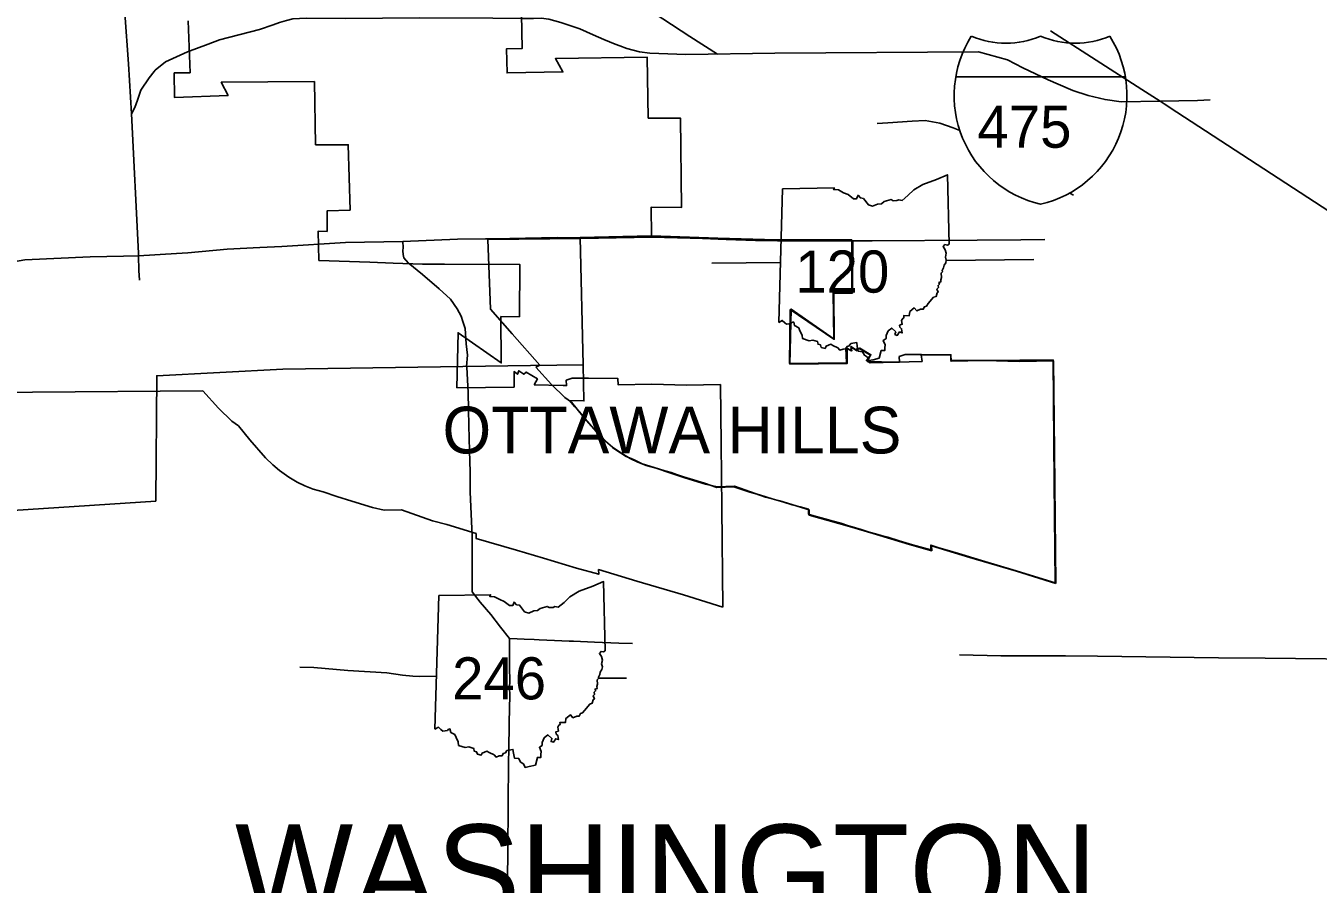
# Model space of a CAD drawing. Extents: x -232 to 448, y 619 to 1059.
# Drawn here: x 128.82 to 157.16, y 925.75 to 944.57 of the extents above; entities that cross this region are included whole.
import ezdxf

# ---------------------------------------------------------------- set-up
doc = ezdxf.new("R2010")
doc.units = 0
doc.layers.add('Default', color=7, linetype='Continuous')

msp = doc.modelspace()

# ---------------------------------------------------------------- linework, layer by layer
at = {"layer": 'Default'}
for p, q in [((149.212, 943.453), (152.932, 943.453)), ((145.332, 938.071), (145.414, 941)), ((145.332, 938.071), (145.414, 941)), ((137.791, 929.15), (137.873, 932.079)), ((137.791, 929.15), (137.873, 932.079))]:
    msp.add_line(p, q, dxfattribs=at)
for points in [[(142.542, 939.966), (142.53, 940.597), (143.197, 940.588), (143.174, 942.551), (142.47, 942.55), (142.445, 943.886), (140.432, 943.857), (140.597, 943.564), (139.374, 943.542), (139.361, 944.072), (139.707, 944.078), (139.685, 945.215), (143.284, 945.238), (143.246, 947.957), (145.167, 947.976), (145.165, 948.173), (140.633, 950.343), (140.619, 950.627), (145.149, 950.658), (145.086, 956.091), (145.054, 958.769)], [(143.987, 943.951), (143.381, 944.34), (142.789, 944.725), (142.086, 945.181), (141.31, 945.696), (141.182, 945.78)], [(131.138, 942.647), (131.072, 943.744), (130.99, 944.853)], [(132.38, 944.682), (132.423, 943.545), (132.075, 943.541), (132.078, 943.003), (133.254, 943.048), (133.105, 943.337), (135.151, 943.353)], [(132.818, 944.175), (133.069, 944.27), (133.944, 944.492), (134.245, 944.598), (134.383, 944.65), (134.537, 944.689), (134.675, 944.726), (134.97, 944.744), (135.833, 944.734), (137.454, 944.748), (139.058, 944.744), (139.679, 944.739)], [(139.679, 944.739), (139.952, 944.736), (140.119, 944.744), (140.287, 944.721), (140.553, 944.65), (140.965, 944.508), (141.264, 944.375), (141.496, 944.276), (141.745, 944.17), (141.848, 944.133)], [(153.293, 943.18), (151.289, 944.468)], [(131.637, 943.573), (131.658, 943.6), (131.88, 943.788), (132.362, 944.003), (132.818, 944.175)], [(141.848, 944.133), (141.998, 944.079), (142.28, 944.003), (142.503, 943.978), (143.291, 943.944), (145.246, 943.972), (149.707, 944.004), (150.348, 943.832), (150.684, 943.655), (151.237, 943.391)], [(131.138, 942.647), (131.213, 942.784), (131.271, 942.942), (131.345, 943.163), (131.525, 943.431), (131.637, 943.573)], [(151.237, 943.391), (151.456, 943.294), (151.779, 943.156), (152.118, 943.045), (152.487, 942.958), (152.839, 942.91), (153.694, 942.922)], [(135.151, 943.353), (135.174, 941.968)], [(153.785, 942.863), (153.694, 942.922), (153.293, 943.18)], [(153.694, 942.922), (154.515, 942.935), (154.788, 942.949)], [(154.06, 942.684), (153.785, 942.863)], [(131.287, 939.587), (131.138, 942.647)], [(158.045, 940.085), (154.06, 942.684)], [(147.487, 942.432), (147.721, 942.445), (148.256, 942.481), (148.544, 942.496), (148.861, 942.441), (149.156, 942.336), (149.301, 942.276)], [(135.174, 941.968), (135.89, 941.967), (135.935, 940.534)], [(145.414, 941), (146.55, 941.019), (146.532, 940.984), (146.64, 940.976), (146.753, 940.914), (146.85, 940.874), (146.968, 940.781), (147.038, 940.782), (147.068, 940.858), (147.122, 940.8), (147.186, 940.789), (147.297, 940.649), (147.388, 940.618), (147.498, 940.667), (147.58, 940.674), (147.639, 940.722), (147.795, 940.763), (147.839, 940.738), (147.921, 940.743), (147.963, 940.761), (148.035, 940.745), (148.162, 940.852), (148.292, 940.977), (148.493, 941.096), (148.793, 941.208), (149.03, 941.308), (149.064, 939.788)], [(145.414, 941), (146.55, 941.019), (146.532, 940.984), (146.64, 940.976), (146.753, 940.914), (146.85, 940.874), (146.968, 940.781), (147.038, 940.782), (147.068, 940.858), (147.122, 940.8), (147.186, 940.789), (147.297, 940.649), (147.388, 940.618), (147.498, 940.667), (147.58, 940.674), (147.639, 940.722), (147.795, 940.763), (147.839, 940.738), (147.921, 940.743), (147.963, 940.761), (148.035, 940.745), (148.162, 940.852), (148.292, 940.977), (148.493, 941.096), (148.793, 941.208), (149.03, 941.308), (149.064, 939.788)], [(151.713, 940.908), (151.792, 940.861)], [(135.935, 940.534), (135.43, 940.52), (135.425, 940.065)], [(135.425, 940.065), (135.231, 940.075), (135.247, 939.425)], [(132.124, 939.584), (132.369, 939.599), (133.232, 939.677), (133.951, 939.713)], [(133.951, 939.713), (134.436, 939.737), (135.826, 939.822), (137.086, 939.842)], [(137.086, 939.842), (138.284, 939.895), (138.9, 939.903)], [(137.086, 939.842), (137.095, 939.717), (137.088, 939.639), (137.095, 939.557), (137.108, 939.485), (137.207, 939.379), (137.517, 939.122), (137.886, 938.805), (138.133, 938.578), (138.28, 938.365), (138.368, 938.208), (138.406, 938.092), (138.451, 937.937), (138.477, 937.604), (138.503, 937.353), (138.486, 937.107), (138.487, 937.091)], [(138.9, 939.903), (139.083, 939.906), (140.472, 939.935), (141.528, 939.926), (142.29, 939.963), (142.472, 939.956)], [(140.991, 939.912), (138.952, 939.886)], [(138.952, 939.886), (139.008, 938.358)], [(141.042, 937.141), (140.979, 939.932), (142.542, 939.966)], [(142.549, 939.942), (140.991, 939.912)], [(142.472, 939.956), (143.127, 939.93), (143.314, 939.928), (144.179, 939.888), (144.831, 939.878), (145.298, 939.882), (146.451, 939.864), (146.793, 939.863)], [(142.542, 939.966), (143.994, 939.919), (145.275, 939.885), (146.93, 939.88)], [(146.537, 938.714), (146.946, 938.712), (146.954, 939.86), (145.3, 939.862), (144.82, 939.864), (144.18, 939.889), (143.663, 939.911), (142.549, 939.942)], [(150.618, 937.245), (149.106, 937.233), (149.106, 937.363), (148.456, 937.363), (148.472, 937.216), (147.336, 937.184), (147.254, 937.233), (147.352, 937.363), (147.108, 937.509), (147.011, 937.476), (146.913, 937.541), (146.93, 937.444), (146.8, 937.509), (146.816, 937.184), (145.566, 937.168), (145.582, 938.353), (146.54, 937.703), (146.524, 938.727), (146.93, 938.727), (146.93, 939.88)], [(146.793, 939.863), (147.382, 939.86), (149.683, 939.875)], [(149.064, 939.788), (149.029, 939.767), (148.975, 939.777), (148.938, 939.734), (148.983, 939.663), (149.005, 939.588), (148.986, 939.505), (149.004, 939.437), (148.992, 939.38), (148.957, 939.323), (148.946, 939.269), (148.917, 939.211), (148.919, 939.179), (148.891, 939.154), (148.896, 939.059), (148.882, 939.006), (148.887, 938.961), (148.842, 938.949), (148.852, 938.911), (148.824, 938.882), (148.83, 938.833), (148.797, 938.801), (148.829, 938.737), (148.804, 938.717), (148.783, 938.639), (148.725, 938.623), (148.609, 938.482), (148.569, 938.428), (148.523, 938.415), (148.498, 938.36), (148.441, 938.359), (148.356, 938.321), (148.301, 938.387), (148.204, 938.308), (148.193, 938.216), (148.07, 938.219), (148.075, 938.173), (148.048, 938.16), (148.023, 938.114), (148.038, 938.031), (147.98, 938.01), (147.987, 937.963), (148.024, 937.933), (148.04, 937.842), (147.979, 937.861), (147.93, 937.784), (147.878, 937.802), (147.895, 937.867), (147.809, 937.945), (147.727, 937.883), (147.684, 937.782), (147.683, 937.715), (147.622, 937.674), (147.661, 937.579), (147.654, 937.513), (147.656, 937.451), (147.579, 937.453), (147.533, 937.285)], [(149.064, 939.788), (149.029, 939.767), (148.975, 939.777), (148.938, 939.734), (148.983, 939.663), (149.005, 939.588), (148.986, 939.505), (149.004, 939.437), (148.992, 939.38), (148.957, 939.323), (148.946, 939.269), (148.917, 939.211), (148.919, 939.179), (148.891, 939.154), (148.896, 939.059), (148.882, 939.006), (148.887, 938.961), (148.842, 938.949), (148.852, 938.911), (148.824, 938.882), (148.83, 938.833), (148.797, 938.801), (148.829, 938.737), (148.804, 938.717), (148.783, 938.639), (148.725, 938.623), (148.609, 938.482), (148.569, 938.428), (148.523, 938.415), (148.498, 938.36), (148.441, 938.359), (148.356, 938.321), (148.301, 938.387), (148.204, 938.308), (148.193, 938.216), (148.07, 938.219), (148.075, 938.173), (148.048, 938.16), (148.023, 938.114), (148.038, 938.031), (147.98, 938.01), (147.987, 937.963), (148.024, 937.933), (148.04, 937.842), (147.979, 937.861), (147.93, 937.784), (147.878, 937.802), (147.895, 937.867), (147.809, 937.945), (147.727, 937.883), (147.684, 937.782), (147.683, 937.715), (147.622, 937.674), (147.661, 937.579), (147.654, 937.513), (147.656, 937.451), (147.579, 937.453), (147.533, 937.285)], [(149.683, 939.875), (150.637, 939.882), (151.162, 939.887)], [(117.861, 938.93), (119.236, 938.938), (119.978, 938.942), (120.576, 938.943), (121.517, 938.965), (123.244, 938.981), (123.805, 938.96), (124.811, 938.901), (125.624, 938.858), (125.876, 938.862), (126.169, 938.873), (126.746, 938.987), (127.511, 939.17), (128.505, 939.389), (128.801, 939.441), (130.232, 939.508), (130.961, 939.526)], [(130.961, 939.526), (131.29, 939.533)], [(131.29, 939.533), (131.287, 939.587)], [(131.29, 939.533), (132.124, 939.584)], [(131.315, 938.998), (131.3, 939.206), (131.29, 939.533)], [(135.247, 939.425), (136.362, 939.394), (136.878, 939.372), (137.518, 939.347), (137.998, 939.345), (139.652, 939.343), (139.645, 938.195), (139.236, 938.197)], [(149.002, 939.428), (150.926, 939.449)], [(143.861, 939.371), (145.369, 939.387)], [(147.272, 937.217), (147.34, 937.349), (147.094, 937.497), (147.044, 937.449), (146.929, 937.527), (146.901, 937.452), (146.829, 937.509), (146.828, 937.168), (145.575, 937.155), (145.6, 938.362), (146.547, 937.701), (146.537, 938.714)], [(139.008, 938.358), (139.485, 937.821), (140.094, 937.13)], [(139.236, 938.197), (139.245, 937.184), (138.298, 937.845), (138.274, 936.638), (139.527, 936.651), (139.527, 936.992), (139.599, 936.935), (139.628, 937.011), (139.743, 936.932), (139.793, 936.98), (140.039, 936.832), (139.97, 936.7)], [(147.533, 937.285), (147.4, 937.253), (147.308, 937.234), (147.276, 937.31), (147.21, 937.35), (147.167, 937.427), (147.073, 937.438), (147.05, 937.543), (147.04, 937.629), (146.911, 937.608), (146.875, 937.556), (146.829, 937.541), (146.803, 937.489), (146.74, 937.484), (146.673, 937.459), (146.629, 937.511), (146.519, 937.563), (146.47, 937.59), (146.367, 937.548), (146.345, 937.499), (146.262, 937.521), (146.243, 937.576), (146.193, 937.592), (146.182, 937.651), (146.076, 937.682), (145.995, 937.669), (145.851, 937.716), (145.843, 937.793), (145.794, 937.886), (145.768, 937.951), (145.677, 938.001), (145.659, 938.078), (145.63, 938.076), (145.604, 938.045), (145.503, 938.03), (145.463, 938.062), (145.406, 938.116), (145.332, 938.071)], [(147.533, 937.285), (147.4, 937.253), (147.308, 937.234), (147.276, 937.31), (147.21, 937.35), (147.167, 937.427), (147.073, 937.438), (147.05, 937.543), (147.04, 937.629), (146.911, 937.608), (146.875, 937.556), (146.829, 937.541), (146.803, 937.489), (146.74, 937.484), (146.673, 937.459), (146.629, 937.511), (146.519, 937.563), (146.47, 937.59), (146.367, 937.548), (146.345, 937.499), (146.262, 937.521), (146.243, 937.576), (146.193, 937.592), (146.182, 937.651), (146.076, 937.682), (145.995, 937.669), (145.851, 937.716), (145.843, 937.793), (145.794, 937.886), (145.768, 937.951), (145.677, 938.001), (145.659, 938.078), (145.63, 938.076), (145.604, 938.045), (145.503, 938.03), (145.463, 938.062), (145.406, 938.116), (145.332, 938.071)], [(149.847, 937.236), (149.108, 937.219), (149.105, 937.357), (148.462, 937.364), (148.1, 937.366), (147.972, 937.32), (147.977, 937.201), (147.902, 937.202), (147.272, 937.217)], [(150.612, 937.214), (149.847, 937.236)], [(150.618, 937.245), (151.349, 937.245), (151.372, 934.574), (151.395, 932.36), (150.539, 932.62)], [(151.358, 937.226), (150.612, 937.214)], [(151.405, 932.342), (151.381, 934.517), (151.369, 935.926), (151.358, 937.226)], [(131.674, 934.149), (131.689, 936.9), (134.454, 937.043), (139.887, 937.125), (141.042, 937.141)], [(138.487, 937.091), (138.517, 936.537), (138.529, 936.159), (138.535, 935.812), (138.55, 935.257), (138.56, 934.793), (138.567, 934.377)], [(140.094, 937.13), (140.002, 937.087)], [(140.002, 937.087), (140.346, 936.708), (140.641, 936.423), (140.786, 936.321)], [(150.539, 932.62), (150.12, 932.747), (149.777, 932.848), (149.344, 932.98), (149.075, 933.064), (148.82, 933.136), (148.663, 933.187), (148.668, 933.082), (148.264, 933.191), (147.968, 933.284), (147.725, 933.358), (147.576, 933.4), (147.449, 933.434), (147.314, 933.474), (147.135, 933.528), (147.012, 933.568), (146.841, 933.617), (146.688, 933.665), (146.52, 933.709), (146.341, 933.762), (146.182, 933.806), (146.026, 933.853), (145.979, 933.867), (145.986, 933.972), (145.803, 934.027), (145.621, 934.073), (145.441, 934.132), (145.184, 934.204), (144.909, 934.288), (144.696, 934.351), (144.519, 934.406), (144.345, 934.465), (143.975, 934.451), (143.703, 934.547), (143.458, 934.619), (143.242, 934.682), (143.085, 934.737), (142.969, 934.777), (142.834, 934.813), (142.599, 934.886), (142.332, 934.972), (142.244, 935.016), (142.171, 935.05), (142.097, 935.087), (141.983, 935.127), (141.857, 935.21), (141.777, 935.264), (141.686, 935.328), (141.534, 935.471), (141.444, 935.566), (141.341, 935.668), (141.217, 935.792), (141.107, 935.922), (140.959, 936.11), (140.858, 936.22), (140.744, 936.356), (141.059, 936.35), (141.042, 937.141)], [(139.97, 936.7), (140.6, 936.686), (140.676, 936.684), (140.671, 936.803), (140.799, 936.849), (141.161, 936.847), (141.803, 936.84), (141.806, 936.702), (142.545, 936.72)], [(142.545, 936.72), (143.31, 936.697)], [(143.31, 936.697), (144.056, 936.709)], [(144.056, 936.709), (144.067, 935.409), (144.079, 934.001), (144.103, 931.825)], [(132.7, 936.57), (128.966, 936.544), (127.156, 936.506), (126.227, 936.473), (125.618, 936.43), (124.23, 936.312)], [(133.485, 935.805), (133.34, 935.906), (133.045, 936.191), (132.7, 936.57)], [(140.786, 936.321), (141.032, 936.011), (141.375, 935.621), (141.534, 935.465), (141.683, 935.337), (141.89, 935.194), (142.071, 935.083), (142.239, 935.005), (142.426, 934.933), (142.639, 934.872), (142.944, 934.773), (143.269, 934.664), (143.726, 934.526), (143.982, 934.468), (144.361, 934.477), (145.043, 934.238), (145.352, 934.157), (146, 933.959)], [(138.698, 933.442), (138.05, 933.64), (137.741, 933.721), (137.059, 933.961), (136.68, 933.952), (136.424, 934.009), (135.967, 934.147), (135.642, 934.256), (135.338, 934.356), (135.124, 934.416), (134.938, 934.488), (134.77, 934.566), (134.589, 934.677), (134.381, 934.82), (134.233, 934.949), (134.073, 935.104), (133.731, 935.495), (133.485, 935.805)], [(138.567, 934.377), (138.567, 934.355), (138.604, 933.384), (138.609, 932.163), (138.782, 931.938), (139.013, 931.664), (139.228, 931.387), (139.429, 931.139)], [(131.674, 934.149), (123.263, 933.603), (115.502, 933.584), (112.51, 933.646), (112.513, 933.427)], [(146, 933.959), (145.997, 933.846), (146.883, 933.593), (147.477, 933.418), (148.196, 933.2), (148.686, 933.065), (148.682, 933.168), (149.519, 932.916), (150.543, 932.612)], [(143.242, 932.095), (142.218, 932.399), (141.381, 932.651), (141.384, 932.548), (140.894, 932.683), (140.175, 932.902), (139.582, 933.076), (138.696, 933.329), (138.698, 933.442)], [(137.873, 932.079), (139.01, 932.098), (138.992, 932.062), (139.099, 932.055), (139.213, 931.992), (139.309, 931.953), (139.427, 931.86), (139.498, 931.861), (139.528, 931.937), (139.582, 931.878), (139.646, 931.868), (139.756, 931.727), (139.848, 931.697), (139.957, 931.745), (140.039, 931.753), (140.099, 931.8), (140.255, 931.841), (140.299, 931.817), (140.381, 931.822), (140.423, 931.84), (140.495, 931.824), (140.622, 931.93), (140.752, 932.056), (140.953, 932.174), (141.252, 932.286), (141.49, 932.387), (141.524, 930.867)], [(137.873, 932.079), (139.01, 932.098), (138.992, 932.062), (139.099, 932.055), (139.213, 931.992), (139.309, 931.953), (139.427, 931.86), (139.498, 931.861), (139.528, 931.937), (139.582, 931.878), (139.646, 931.868), (139.756, 931.727), (139.848, 931.697), (139.957, 931.745), (140.039, 931.753), (140.099, 931.8), (140.255, 931.841), (140.299, 931.817), (140.381, 931.822), (140.423, 931.84), (140.495, 931.824), (140.622, 931.93), (140.752, 932.056), (140.953, 932.174), (141.252, 932.286), (141.49, 932.387), (141.524, 930.867)], [(150.543, 932.612), (151.405, 932.342)], [(144.103, 931.825), (143.242, 932.095)], [(139.429, 931.139), (139.428, 930.506), (139.432, 930.21), (139.425, 930.058), (139.431, 929.897), (139.419, 929.295), (139.408, 928.673), (139.406, 928.458)], [(139.429, 931.139), (139.591, 931.131), (139.745, 931.125), (139.97, 931.115), (140.075, 931.112), (140.416, 931.093), (140.735, 931.084), (140.832, 931.079)], [(140.832, 931.079), (141.291, 931.055), (141.827, 931.038), (142.126, 931.028)], [(141.524, 930.867), (141.489, 930.845), (141.434, 930.856), (141.398, 930.813), (141.443, 930.742), (141.464, 930.667), (141.445, 930.584), (141.464, 930.515), (141.451, 930.458), (141.417, 930.401), (141.405, 930.347), (141.376, 930.29), (141.379, 930.258), (141.351, 930.233), (141.356, 930.138), (141.342, 930.085), (141.347, 930.039), (141.302, 930.028), (141.312, 929.99), (141.283, 929.961), (141.29, 929.911), (141.257, 929.879), (141.289, 929.816), (141.263, 929.795), (141.242, 929.718), (141.185, 929.702), (141.069, 929.56), (141.028, 929.507), (140.982, 929.493), (140.957, 929.438), (140.901, 929.438), (140.815, 929.4), (140.76, 929.465), (140.664, 929.386), (140.652, 929.295), (140.53, 929.298), (140.535, 929.252), (140.508, 929.238), (140.483, 929.192), (140.497, 929.11), (140.44, 929.089), (140.447, 929.041), (140.484, 929.012), (140.5, 928.921), (140.439, 928.939), (140.389, 928.862), (140.338, 928.88), (140.355, 928.946), (140.268, 929.024), (140.186, 928.961), (140.144, 928.861), (140.143, 928.794), (140.082, 928.753), (140.121, 928.658), (140.114, 928.592), (140.115, 928.53), (140.039, 928.532), (139.993, 928.364)], [(141.524, 930.867), (141.489, 930.845), (141.434, 930.856), (141.398, 930.813), (141.443, 930.742), (141.464, 930.667), (141.445, 930.584), (141.464, 930.515), (141.451, 930.458), (141.417, 930.401), (141.405, 930.347), (141.376, 930.29), (141.379, 930.258), (141.351, 930.233), (141.356, 930.138), (141.342, 930.085), (141.347, 930.039), (141.302, 930.028), (141.312, 929.99), (141.283, 929.961), (141.29, 929.911), (141.257, 929.879), (141.289, 929.816), (141.263, 929.795), (141.242, 929.718), (141.185, 929.702), (141.069, 929.56), (141.028, 929.507), (140.982, 929.493), (140.957, 929.438), (140.901, 929.438), (140.815, 929.4), (140.76, 929.465), (140.664, 929.386), (140.652, 929.295), (140.53, 929.298), (140.535, 929.252), (140.508, 929.238), (140.483, 929.192), (140.497, 929.11), (140.44, 929.089), (140.447, 929.041), (140.484, 929.012), (140.5, 928.921), (140.439, 928.939), (140.389, 928.862), (140.338, 928.88), (140.355, 928.946), (140.268, 929.024), (140.186, 928.961), (140.144, 928.861), (140.143, 928.794), (140.082, 928.753), (140.121, 928.658), (140.114, 928.592), (140.115, 928.53), (140.039, 928.532), (139.993, 928.364)], [(149.296, 930.784), (150.203, 930.756), (150.214, 930.756)], [(150.214, 930.756), (151.403, 930.758)], [(151.403, 930.758), (151.619, 930.756)], [(151.619, 930.756), (152.322, 930.748)], [(152.322, 930.748), (154.971, 930.717)], [(154.971, 930.717), (155.998, 930.705)], [(155.998, 930.705), (158.647, 930.675)], [(134.825, 930.511), (135.134, 930.5), (135.879, 930.434), (136.733, 930.387), (137.079, 930.338), (137.306, 930.314), (137.459, 930.302), (137.824, 930.315)], [(141.366, 930.27), (141.493, 930.268), (141.913, 930.27), (141.994, 930.267)], [(139.993, 928.364), (139.86, 928.332), (139.768, 928.312), (139.736, 928.389), (139.67, 928.429), (139.627, 928.506), (139.532, 928.516), (139.51, 928.622), (139.499, 928.708), (139.37, 928.686), (139.335, 928.634), (139.289, 928.62), (139.262, 928.567), (139.2, 928.563), (139.133, 928.538), (139.089, 928.59), (138.979, 928.642), (138.93, 928.668), (138.826, 928.627), (138.804, 928.577), (138.722, 928.599), (138.703, 928.654), (138.653, 928.671), (138.642, 928.729), (138.536, 928.76), (138.454, 928.748), (138.311, 928.795), (138.302, 928.871), (138.253, 928.965), (138.228, 929.03), (138.137, 929.08), (138.119, 929.157), (138.09, 929.154), (138.063, 929.123), (137.963, 929.109), (137.922, 929.14), (137.866, 929.194), (137.791, 929.15)], [(139.993, 928.364), (139.86, 928.332), (139.768, 928.312), (139.736, 928.389), (139.67, 928.429), (139.627, 928.506), (139.532, 928.516), (139.51, 928.622), (139.499, 928.708), (139.37, 928.686), (139.335, 928.634), (139.289, 928.62), (139.262, 928.567), (139.2, 928.563), (139.133, 928.538), (139.089, 928.59), (138.979, 928.642), (138.93, 928.668), (138.826, 928.627), (138.804, 928.577), (138.722, 928.599), (138.703, 928.654), (138.653, 928.671), (138.642, 928.729), (138.536, 928.76), (138.454, 928.748), (138.311, 928.795), (138.302, 928.871), (138.253, 928.965), (138.228, 929.03), (138.137, 929.08), (138.119, 929.157), (138.09, 929.154), (138.063, 929.123), (137.963, 929.109), (137.922, 929.14), (137.866, 929.194), (137.791, 929.15)], [(139.406, 928.458), (139.39, 926.494), (139.379, 925.832)]]:
    msp.add_lwpolyline(points, dxfattribs=at)
for centre, radius, start, end in [((151.622, 943.044), 2.445, 147.8216, 256.9941), ((151.622, 943.044), 2.445, 147.8216, 256.9941), ((150.313, 946.143), 1.951, 247.0848, 292.9105), ((150.313, 946.143), 1.951, 247.0848, 292.9105), ((150.522, 943.044), 2.445, 283.0065, 32.1787), ((151.832, 946.143), 1.951, 247.0916, 292.9084), ((150.522, 943.044), 2.445, 283.0065, 32.1787), ((151.832, 946.143), 1.951, 247.0916, 292.9084)]:
    msp.add_arc(centre, radius, start, end, dxfattribs=at)

# ---------------------------------------------------------------- texts
for s, height, p in [('475', 0.9234, (149.688, 941.901)), ('120', 0.9234, (145.694, 938.724)), ('OTTAWA HILLS', 1.026, (137.957, 935.197)), ('246', 0.9234, (138.168, 929.803)), ('WASHINGTON', 2.052, (133.407, 925.008))]:
    msp.add_text(s, height=height, dxfattribs=at).set_placement(p)

doc.saveas('drawing.dxf')
